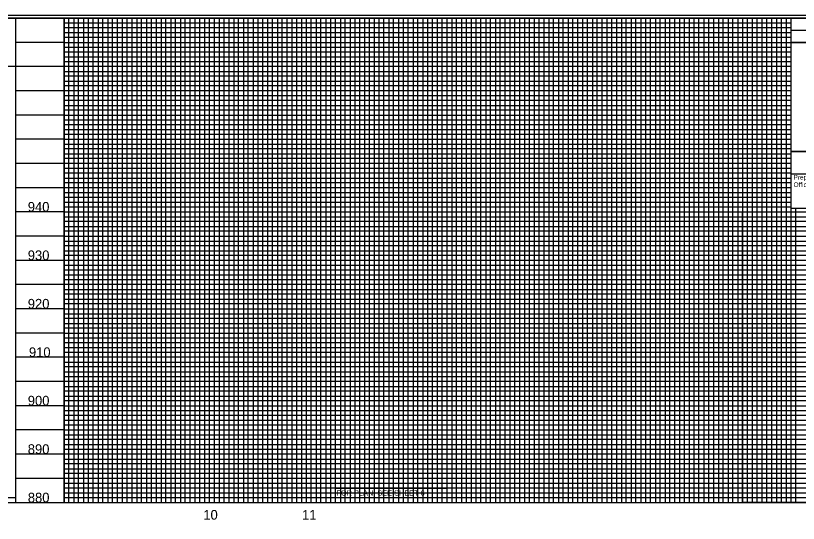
# Model space of a CAD drawing. Extents: x 1967929 to 1975641, y 546296 to 568534.
# Drawn here: x 1970531 to 1971339, y 564687 to 565211 of the extents above; entities that cross this region are included whole.
import ezdxf

# ---------------------------------------------------------------- set-up
doc = ezdxf.new("R2010")
doc.units = 0
for name, color, linetype in [('Exist Vertical Profile Horizontal Axis Label Major', 7, 'Continuous'), ('Exist Vertical Profile Vertical Axis Label', 7, 'Continuous'), ('Old_Level_2', 7, 'Continuous'), ('Prop Grid Mask', 7, 'Continuous'), ('Scratch_Level_1', 7, 'Continuous'), ('Scratch_Level_3', 7, 'Continuous'), ('Sheet Plot Border Inside CELL', 7, 'Continuous'), ('Sheet Profile CELL', 7, 'Continuous'), ('Sheet Profile Grid Major CELL', 7, 'Continuous'), ('Sheet Profile Grid Middle CELL', 7, 'Continuous'), ('Sheet Profile Grid Minor CELL', 7, 'Continuous')]:
    doc.layers.add(name, color=color, linetype=linetype)

msp = doc.modelspace()

# ---------------------------------------------------------------- linework, layer by layer
at = {"layer": 'Prop Grid Mask'}
msp.add_lwpolyline([(1970861.48, 564723.9), (1970976.36, 564723.9), (1970976.36, 564713.87), (1970861.48, 564713.87)], close=True, dxfattribs=at)
at = {"layer": 'Scratch_Level_1'}
for p, q in [((1971331.4, 565047.81), (1971331.4, 565071.31)), ((1971331.4, 565071.31), (1971531.44, 565071.31)), ((1971531.44, 565047.81), (1971331.4, 565047.81))]:
    msp.add_line(p, q, dxfattribs=at)
at = {"layer": 'Scratch_Level_3'}
for points in [[(1970081.45, 565208.86), (1970081.45, 564708.86), (1971481.45, 564708.86), (1971481.45, 565012.51), (1971331.4, 565012.51), (1971331.4, 565208.86)], [(1970081.45, 565208.86), (1970081.45, 564708.86), (1971331.45, 564708.86), (1971331.45, 564977.21), (1971331.45, 564977.21), (1971331.45, 565208.86)], [(1970981.45, 564708.86), (1971181.45, 564708.86), (1971181.45, 565158.86), (1970981.45, 565158.86)], [(1971281.45, 565008.86), (1971481.45, 565008.86), (1971481.45, 564708.86), (1971281.45, 564708.86)]]:
    msp.add_lwpolyline(points, close=True, dxfattribs=at)
at = {"layer": 'Sheet Plot Border Inside CELL'}
msp.add_lwpolyline([(1969877.45, 564156.31), (1971543.95, 564156.31), (1971543.95, 565211.41), (1969877.45, 565211.41)], close=True, dxfattribs=at)
at = {"layer": 'Sheet Profile CELL'}
for p, q in [((1971331.4, 565196.31), (1971531.45, 565196.31)), ((1970031.45, 564708.86), (1971531.45, 564708.86))]:
    msp.add_line(p, q, dxfattribs=at)
for points in [[(1971531.45, 565208.86), (1970031.45, 565208.86), (1970031.45, 564158.86), (1971531.45, 564158.86)], [(1971331.4, 565208.86), (1971531.45, 565208.86), (1971531.45, 565183.81), (1971331.4, 565183.81)], [(1971331.4, 565183.81), (1971431.45, 565183.81), (1971431.45, 565071.31), (1971331.4, 565071.31)]]:
    msp.add_lwpolyline(points, close=True, dxfattribs=at)
msp.add_lwpolyline([(1971531.45, 565012.51), (1971331.4, 565012.51), (1971331.4, 565047.81)], dxfattribs=at)
at = {"layer": 'Sheet Profile Grid Major CELL'}
for points in [[(1970531.35, 565158.86), (1970031.4, 565158.86), (1970031.4, 565208.86), (1971331.4, 565208.86)], [(1970531.4, 565208.86), (1970531.4, 564708.86), (1970581.4, 564708.86), (1970581.4, 565208.86)], [(1970581.4, 565208.86), (1970581.4, 564708.86), (1970631.4, 564708.86), (1970631.4, 565208.86)], [(1970681.4, 565208.86), (1970681.4, 564708.86), (1970731.4, 564708.86), (1970731.4, 565208.86)], [(1970781.4, 565208.86), (1970781.4, 564708.86), (1970831.4, 564708.86), (1970831.4, 565208.86)], [(1970881.4, 565208.86), (1970881.4, 564708.86), (1970931.4, 564708.86), (1970931.4, 565208.86)], [(1970981.4, 565208.86), (1970981.4, 564708.86), (1971031.4, 564708.86), (1971031.4, 565208.86)], [(1971081.4, 565208.86), (1971081.4, 564708.86), (1971131.4, 564708.86), (1971131.4, 565208.86)], [(1971181.4, 565208.86), (1971181.4, 564708.86), (1971231.4, 564708.86), (1971231.4, 565208.86)], [(1971281.4, 565208.86), (1971281.4, 564708.86), (1971331.4, 564708.86), (1971331.4, 565208.86)], [(1970581.4, 565158.86), (1970531.4, 565158.86)], [(1971331.4, 565158.86), (1970581.4, 565158.86)], [(1970581.4, 565108.86), (1970531.4, 565108.86)], [(1970581.4, 565108.86), (1971331.4, 565108.86)], [(1970581.4, 565058.86), (1970531.4, 565058.86)], [(1971331.4, 565058.86), (1970581.4, 565058.86)], [(1970581.4, 565008.86), (1970531.4, 565008.86)], [(1970581.4, 565008.86), (1971481.4, 565008.86)], [(1970581.4, 564958.86), (1970531.4, 564958.86)], [(1971531.4, 564958.86), (1970581.4, 564958.86)], [(1970581.4, 564908.86), (1970531.4, 564908.86)], [(1970581.4, 564908.86), (1971531.4, 564908.86)], [(1970581.4, 564858.86), (1970531.4, 564858.86)], [(1971531.4, 564858.86), (1970581.4, 564858.86)], [(1970581.4, 564808.86), (1970531.4, 564808.86)], [(1970581.4, 564808.86), (1971531.4, 564808.86)], [(1970581.4, 564758.86), (1970531.4, 564758.86)], [(1971531.4, 564758.86), (1970581.4, 564758.86)]]:
    msp.add_lwpolyline(points, dxfattribs=at)
at = {"layer": 'Sheet Profile Grid Middle CELL'}
for p, q in [((1970606.4, 564708.86), (1970606.4, 565208.86)), ((1970556.4, 564708.86), (1970606.4, 564708.86)), ((1970756.45, 564708.86), (1970806.45, 564708.86)), ((1970856.45, 564708.86), (1970906.45, 564708.86)), ((1970906.45, 564708.86), (1970906.45, 564708.86))]:
    msp.add_line(p, q, dxfattribs=at)
for points in [[(1970656.4, 565208.86), (1970656.4, 564708.86), (1970706.4, 564708.86), (1970706.4, 565208.86)], [(1970756.4, 565208.86), (1970756.4, 564708.86), (1970806.4, 564708.86), (1970806.4, 565208.86)], [(1970856.4, 565208.86), (1970856.4, 564708.86), (1970906.4, 564708.86), (1970906.4, 565208.86)], [(1970956.4, 565208.86), (1970956.4, 564708.86), (1971006.4, 564708.86), (1971006.4, 565208.86)], [(1971056.4, 565208.86), (1971056.4, 564708.86), (1971106.4, 564708.86), (1971106.4, 565208.86)], [(1971156.4, 565208.86), (1971156.4, 564708.86), (1971206.4, 564708.86), (1971206.4, 565208.86)], [(1971256.4, 565208.86), (1971256.4, 564708.86), (1971306.4, 564708.86), (1971306.4, 565208.86)], [(1970581.4, 565183.86), (1970531.4, 565183.86)], [(1970581.4, 565183.86), (1971331.4, 565183.86)], [(1970581.4, 565133.86), (1970531.4, 565133.86)], [(1971331.4, 565133.86), (1970581.4, 565133.86)], [(1970581.4, 565083.86), (1970531.4, 565083.86)], [(1970581.4, 565083.86), (1971331.4, 565083.86)], [(1970581.4, 565033.86), (1970531.4, 565033.86)], [(1971331.4, 565033.86), (1970581.4, 565033.86)], [(1970581.4, 564983.86), (1970531.4, 564983.86)], [(1970581.4, 564983.86), (1971481.4, 564983.86)], [(1970581.4, 564933.86), (1970531.4, 564933.86)], [(1971531.4, 564933.86), (1970581.4, 564933.86)], [(1970581.4, 564883.86), (1970531.4, 564883.86)], [(1970581.4, 564883.86), (1971531.4, 564883.86)], [(1970581.4, 564833.86), (1970531.4, 564833.86)], [(1971531.4, 564833.86), (1970581.4, 564833.86)], [(1970581.4, 564783.86), (1970531.4, 564783.86)], [(1970581.4, 564783.86), (1971531.4, 564783.86)], [(1970581.4, 564733.86), (1970531.4, 564733.86)], [(1971531.4, 564733.86), (1970581.4, 564733.86)]]:
    msp.add_lwpolyline(points, dxfattribs=at)
at = {"layer": 'Sheet Profile Grid Minor CELL'}
for p, q in [((1970586.4, 564708.86), (1970586.4, 565208.86)), ((1970581.4, 564718.86), (1971481.4, 564718.86)), ((1970566.4, 564708.86), (1970571.4, 564708.86)), ((1970576.4, 564708.86), (1970586.4, 564708.86)), ((1970776.45, 564708.86), (1970786.45, 564708.86)), ((1970851.45, 564708.86), (1970861.45, 564708.86)), ((1970866.45, 564708.86), (1970871.45, 564708.86)), ((1970886.45, 564708.86), (1970886.45, 564708.86))]:
    msp.add_line(p, q, dxfattribs=at)
for points in [[(1970581.4, 565203.86), (1971331.4, 565203.86)], [(1970591.4, 565208.86), (1970591.4, 564708.86), (1970596.4, 564708.86), (1970596.4, 565208.86)], [(1970601.4, 565208.86), (1970601.4, 564708.86)], [(1970611.4, 564708.86), (1970611.4, 565208.86)], [(1970616.4, 565208.86), (1970616.4, 564708.86), (1970621.4, 564708.86), (1970621.4, 565208.86)], [(1970626.4, 565208.86), (1970626.4, 564708.86), (1970636.4, 564708.86), (1970636.4, 565208.86)], [(1970641.4, 565208.86), (1970641.4, 564708.86), (1970641.4, 564708.86), (1970646.4, 564708.86), (1970646.4, 565208.86)], [(1970651.4, 565208.86), (1970651.4, 564708.86), (1970661.4, 564708.86), (1970661.4, 565208.86)], [(1970666.4, 565208.86), (1970666.4, 564708.86), (1970671.4, 564708.86), (1970671.4, 565208.86)], [(1970676.4, 565208.86), (1970676.4, 564708.86), (1970686.4, 564708.86), (1970686.4, 565208.86)], [(1970681.45, 565203.86), (1970781.45, 565203.86)], [(1970691.4, 565208.86), (1970691.4, 564708.86), (1970696.4, 564708.86), (1970696.4, 565208.86)], [(1970701.4, 565208.86), (1970701.4, 564708.86), (1970711.4, 564708.86), (1970711.4, 565208.86)], [(1970716.4, 565208.86), (1970716.4, 564708.86), (1970721.4, 564708.86), (1970721.4, 565208.86)], [(1970726.4, 565208.86), (1970726.4, 564708.86), (1970736.4, 564708.86), (1970736.4, 565208.86)], [(1970741.4, 565208.86), (1970741.4, 564708.86), (1970746.4, 564708.86), (1970746.4, 565208.86)], [(1970751.4, 565208.86), (1970751.4, 564708.86), (1970761.4, 564708.86), (1970761.4, 565208.86)], [(1970766.4, 565208.86), (1970766.4, 564708.86), (1970771.4, 564708.86), (1970771.4, 565208.86)], [(1970776.4, 565208.86), (1970776.4, 564708.86), (1970786.4, 564708.86), (1970786.4, 565208.86)], [(1970781.45, 565203.86), (1970881.45, 565203.86)], [(1970791.4, 565208.86), (1970791.4, 564708.86)], [(1970791.4, 564708.86), (1970796.4, 564708.86), (1970796.4, 565208.86)], [(1970801.4, 565208.86), (1970801.4, 564708.86), (1970811.4, 564708.86), (1970811.4, 565208.86)], [(1970816.4, 565208.86), (1970816.4, 564708.86), (1970821.4, 564708.86), (1970821.4, 565208.86)], [(1970826.4, 565208.86), (1970826.4, 564708.86), (1970836.4, 564708.86), (1970836.4, 565208.86)], [(1970841.4, 565208.86), (1970841.4, 564708.86), (1970846.4, 564708.86), (1970846.4, 565208.86)], [(1970851.4, 565208.86), (1970851.4, 564708.86), (1970861.4, 564708.86), (1970861.4, 565208.86)], [(1970866.4, 565208.86), (1970866.4, 564708.86), (1970871.4, 564708.86), (1970871.4, 565208.86)], [(1970876.4, 565208.86), (1970876.4, 564708.86), (1970886.4, 564708.86), (1970886.4, 565208.86)], [(1970891.4, 565208.86), (1970891.4, 564708.86), (1970896.4, 564708.86), (1970896.4, 565208.86)], [(1970901.4, 565208.86), (1970901.4, 564708.86), (1970911.4, 564708.86), (1970911.4, 565208.86)], [(1970916.4, 565208.86), (1970916.4, 564708.86), (1970921.4, 564708.86), (1970921.4, 565208.86)], [(1970926.4, 565208.86), (1970926.4, 564708.86), (1970936.4, 564708.86), (1970936.4, 565208.86)], [(1970941.4, 565208.86), (1970941.4, 564708.86), (1970946.4, 564708.86), (1970946.4, 565208.86)], [(1970951.4, 565208.86), (1970951.4, 564708.86), (1970961.4, 564708.86), (1970961.4, 565208.86)], [(1970966.4, 565208.86), (1970966.4, 564708.86), (1970971.4, 564708.86), (1970971.4, 565208.86)], [(1970976.4, 565208.86), (1970976.4, 564708.86), (1970986.4, 564708.86), (1970986.4, 565208.86)], [(1970991.4, 565208.86), (1970991.4, 564708.86), (1970996.4, 564708.86), (1970996.4, 565208.86)], [(1971001.4, 565208.86), (1971001.4, 564708.86), (1971011.4, 564708.86), (1971011.4, 565208.86)], [(1971016.4, 565208.86), (1971016.4, 564708.86), (1971021.4, 564708.86), (1971021.4, 565208.86)], [(1971026.4, 565208.86), (1971026.4, 564708.86), (1971036.4, 564708.86), (1971036.4, 565208.86)], [(1971041.4, 565208.86), (1971041.4, 564708.86), (1971046.4, 564708.86), (1971046.4, 565208.86)], [(1971051.4, 565208.86), (1971051.4, 564708.86), (1971061.4, 564708.86), (1971061.4, 565208.86)], [(1971066.4, 565208.86), (1971066.4, 564708.86), (1971071.4, 564708.86), (1971071.4, 565208.86)], [(1971076.4, 565208.86), (1971076.4, 564708.86), (1971086.4, 564708.86), (1971086.4, 565208.86)], [(1971091.4, 565208.86), (1971091.4, 564708.86), (1971096.4, 564708.86), (1971096.4, 565208.86)], [(1971101.4, 565208.86), (1971101.4, 564708.86)], [(1971101.4, 564708.86), (1971111.4, 564708.86), (1971111.4, 565208.86)], [(1971116.4, 565208.86), (1971116.4, 564708.86), (1971121.4, 564708.86), (1971121.4, 565208.86)], [(1971126.4, 565208.86), (1971126.4, 564708.86), (1971136.4, 564708.86), (1971136.4, 565208.86)], [(1971141.4, 565208.86), (1971141.4, 564708.86), (1971146.4, 564708.86), (1971146.4, 565208.86)], [(1971151.4, 565208.86), (1971151.4, 564708.86), (1971161.4, 564708.86), (1971161.4, 565208.86)], [(1971166.4, 565208.86), (1971166.4, 564708.86), (1971171.4, 564708.86), (1971171.4, 565208.86)], [(1971176.4, 565208.86), (1971176.4, 564708.86), (1971186.4, 564708.86), (1971186.4, 565208.86)], [(1971191.4, 565208.86), (1971191.4, 564708.86), (1971196.4, 564708.86), (1971196.4, 565208.86)], [(1971201.4, 565208.86), (1971201.4, 564708.86), (1971211.4, 564708.86), (1971211.4, 565208.86)], [(1971216.4, 565208.86), (1971216.4, 564708.86), (1971221.4, 564708.86), (1971221.4, 565208.86)], [(1971226.4, 565208.86), (1971226.4, 564708.86), (1971236.4, 564708.86), (1971236.4, 565208.86)], [(1971241.4, 565208.86), (1971241.4, 564708.86), (1971246.4, 564708.86), (1971246.4, 565208.86)], [(1971251.4, 565208.86), (1971251.4, 564708.86), (1971261.4, 564708.86), (1971261.4, 565208.86)], [(1971266.4, 565208.86), (1971266.4, 564708.86), (1971271.4, 564708.86), (1971271.4, 565208.86)], [(1971276.4, 565208.86), (1971276.4, 564708.86), (1971286.4, 564708.86), (1971286.4, 565208.86)], [(1971281.45, 565203.86), (1971331.45, 565203.86)], [(1971291.4, 565208.86), (1971291.4, 564708.86), (1971296.4, 564708.86), (1971296.4, 565208.86)], [(1971301.4, 565208.86), (1971301.4, 564708.86), (1971311.4, 564708.86), (1971311.4, 565208.86)], [(1971316.4, 565208.86), (1971316.4, 564708.86), (1971321.4, 564708.86), (1971321.4, 565208.86)], [(1971326.4, 565208.86), (1971326.4, 564708.86), (1971336.4, 564708.86), (1971336.4, 564977.21)], [(1971326.4, 565208.86), (1971326.4, 564708.86), (1971336.4, 564708.86), (1971336.4, 565012.51)], [(1971331.4, 565198.86), (1970581.4, 565198.86)], [(1970581.4, 565193.86), (1971331.4, 565193.86)], [(1971331.4, 565188.86), (1970581.4, 565188.86)], [(1970581.4, 565178.86), (1971331.4, 565178.86)], [(1971331.4, 565173.86), (1970581.4, 565173.86)], [(1970581.4, 565168.86), (1971331.4, 565168.86)], [(1971331.4, 565163.86), (1970581.4, 565163.86)], [(1970581.4, 565153.86), (1971331.4, 565153.86)], [(1971331.4, 565148.86), (1970581.4, 565148.86)], [(1970581.4, 565143.86), (1971331.4, 565143.86)], [(1971331.4, 565138.86), (1970581.4, 565138.86)], [(1970581.4, 565128.86), (1971331.4, 565128.86)], [(1971331.4, 565123.86), (1970581.4, 565123.86)], [(1970581.4, 565118.86), (1971331.4, 565118.86)], [(1971331.4, 565113.86), (1970581.4, 565113.86)], [(1970581.4, 565103.86), (1971331.4, 565103.86)], [(1971331.4, 565098.86), (1970581.4, 565098.86)], [(1970581.4, 565093.86), (1971331.4, 565093.86)], [(1971331.4, 565088.86), (1970581.4, 565088.86)], [(1970581.4, 565078.86), (1971331.4, 565078.86)], [(1971331.4, 565073.86), (1970581.4, 565073.86)], [(1970581.4, 565068.86), (1971331.4, 565068.86)], [(1971331.4, 565063.86), (1970581.4, 565063.86)], [(1970581.4, 565053.86), (1971331.4, 565053.86)], [(1971331.4, 565048.86), (1970581.4, 565048.86)], [(1970581.4, 565043.86), (1971331.4, 565043.86)], [(1971331.4, 565038.86), (1970581.4, 565038.86)], [(1970581.4, 565028.86), (1971331.4, 565028.86)], [(1971331.4, 565023.86), (1970581.4, 565023.86)], [(1970581.4, 565018.86), (1971331.4, 565018.86)], [(1971331.4, 565013.86), (1970581.4, 565013.86)], [(1970581.4, 565003.86), (1971481.4, 565003.86)], [(1971481.4, 564998.86), (1970581.4, 564998.86)], [(1970581.4, 564993.86), (1971481.4, 564993.86)], [(1971481.4, 564988.86), (1970581.4, 564988.86)], [(1970581.4, 564978.86), (1971481.4, 564978.86)], [(1971481.4, 564973.86), (1970581.4, 564973.86)], [(1970581.4, 564968.86), (1971481.4, 564968.86)], [(1971481.4, 564963.86), (1970581.4, 564963.86)], [(1970581.4, 564953.86), (1971481.4, 564953.86)], [(1971481.4, 564948.86), (1970581.4, 564948.86)], [(1970581.4, 564943.86), (1971481.4, 564943.86)], [(1971481.4, 564938.86), (1970581.4, 564938.86)], [(1970581.4, 564928.86), (1971481.4, 564928.86)], [(1971481.4, 564923.86), (1970581.4, 564923.86)], [(1970581.4, 564918.86), (1971481.4, 564918.86)], [(1971481.4, 564913.86), (1970581.4, 564913.86)], [(1970581.4, 564903.86), (1971481.4, 564903.86)], [(1971481.4, 564898.86), (1970581.4, 564898.86)], [(1970581.4, 564893.86), (1971481.4, 564893.86)], [(1971481.4, 564888.86), (1970581.4, 564888.86)], [(1970581.4, 564878.86), (1971481.4, 564878.86)], [(1971481.4, 564873.86), (1970581.4, 564873.86)], [(1970581.4, 564868.86), (1971481.4, 564868.86)], [(1971481.4, 564863.86), (1970581.4, 564863.86)], [(1970581.4, 564853.86), (1971481.4, 564853.86)], [(1971481.4, 564848.86), (1970581.4, 564848.86)], [(1970581.4, 564843.86), (1971481.4, 564843.86)], [(1971481.4, 564838.86), (1970581.4, 564838.86)], [(1970581.4, 564828.86), (1971481.4, 564828.86)], [(1971481.4, 564823.86), (1970581.4, 564823.86)], [(1970581.4, 564818.86), (1971481.4, 564818.86)], [(1971481.4, 564813.86), (1970581.4, 564813.86)], [(1970581.4, 564803.86), (1971481.4, 564803.86)], [(1971481.4, 564798.86), (1970581.4, 564798.86)], [(1970581.4, 564793.86), (1971481.4, 564793.86)], [(1971481.4, 564788.86), (1970581.4, 564788.86)], [(1970581.4, 564778.86), (1971481.4, 564778.86)], [(1971481.4, 564773.86), (1970581.4, 564773.86)], [(1970581.4, 564768.86), (1971481.4, 564768.86)], [(1971481.4, 564763.86), (1970581.4, 564763.86)], [(1970581.4, 564753.86), (1971481.4, 564753.86)], [(1971481.4, 564748.86), (1970581.4, 564748.86)], [(1970581.4, 564743.86), (1971481.4, 564743.86)], [(1971481.4, 564738.86), (1970581.4, 564738.86)], [(1970581.4, 564728.86), (1971481.4, 564728.86)], [(1971481.4, 564723.86), (1970581.4, 564723.86)], [(1970531.35, 564713.86), (1970081.4, 564713.86), (1970081.4, 564708.86), (1971481.4, 564708.86)], [(1971481.4, 564713.86), (1970581.4, 564713.86)]]:
    msp.add_lwpolyline(points, dxfattribs=at)

# ---------------------------------------------------------------- texts
at = {"layer": 'Exist Vertical Profile Horizontal Axis Label Major'}
for s, p in [('10', (1970725.03, 564691.27)), ('11', (1970826.87, 564691.27))]:
    msp.add_text(s, height=10, dxfattribs=at).set_placement(p)
at = {"layer": 'Exist Vertical Profile Vertical Axis Label'}
for s, p in [('940', (1970543.91, 565009.11)), ('930', (1970543.91, 564959.11)), ('920', (1970543.91, 564909.11)), ('910', (1970545.11, 564859.11)), ('900', (1970543.91, 564809.11)), ('890', (1970543.91, 564759.11)), ('880', (1970543.96, 564709.11))]:
    msp.add_text(s, height=10, dxfattribs=at).set_placement(p)
at = {"layer": 'Old_Level_2'}
for s, height, p in [('Prepared in the ', 4.8186, (1971333.95, 565042.31)), ('Office of:', 4.819, (1971333.95, 565034.56))]:
    msp.add_text(s, height=height, dxfattribs=at).set_placement(p)
at = {"layer": 'Prop Grid Mask'}
msp.add_text('FOR PLAN: SEE SHEET 6', height=5.4932, dxfattribs=at).set_placement((1970862.37, 564716.16))

doc.saveas('drawing.dxf')
